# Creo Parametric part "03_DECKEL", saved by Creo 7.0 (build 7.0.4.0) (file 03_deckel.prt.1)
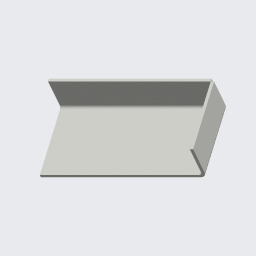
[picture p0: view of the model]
Units: millimeter Kilogram Sec (mmKs); MM, KILOGRAM, SECS
Materials in the file: S235JRG2

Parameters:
  SMT_PART_BEND_ALLOW_FACTOR_TYPE = "Y FACTOR"
  SMT_DFLT_RADIUS_SIDE = "Inside"
  SMT_DFLT_CRNR_REL_TYPE = "V Notch"
  SMT_DFLT_CRNR_REL_DEPTH_TYPE = "Blind"
  SMT_DFLT_BEND_REL_TYPE = "Rip"
  SMT_DFLT_BEND_REL_DEPTH_TYPE = "Up to Bend"
  SMT_DFLT_EDGE_TREA_TYPE = "Open"
  PTC_MATERIAL_NAME = "S235JRG2"
  MATERIAL = "S235JRG2"
  BENENNUNG = "XXX"
  DATUM = "XX.XX.XX"
  ERSTELLER = "ARINDA"
  TEILETYP = "Fertigungsteil"
  SELECT_EN_NAME = "S235JRG2"
  SELECT_DIN_NAME = "RSt37-2"
  SELECT_DIN_NUMBER = "1.0038"
  SELECT_ASTM_NAME = "A 283 M Grade 2"
  MATERIAL_GROUP = "ME_ST_Baustahl"
  STANDARD_EN_DELIVERYSPEC = "DIN EN 10025"
  STANDARD_DIN_DELIVERYSPEC = "DIN 17100"

Other parameters: SMT_THICKNESS, SMT_PART_BEND_ALLOWANCE_FACTOR, SMT_UPDATE_BEND_ALLOW_INFO, SMT_DFLT_BEND_RADIUS, SMT_DFLT_BEND_ANGLE, SMT_DFLT_CRNR_REL_WIDTH, SMT_DFLT_CRNR_REL_DEPTH, SMT_DFLT_BEND_REL_WIDTH, SMT_DFLT_BEND_REL_DEPTH, SMT_DFLT_BEND_REL_ANGLE, SMT_GAP, SMT_DFLT_EDGE_TREA_WIDTH, SMT_DFLT_MITER_CUT_WIDTH, SMT_DFLT_MITER_CUT_OFFSET, MASSE, SMT_DFLT_BEND_REL_LENGTH, D9, D11, D12, D13, D14, D15, D16, D17, D18, D19, D21, D24, D30, D34, D36, D37, D38, D39, D40, D41, D42, D43, D44, D49, D53, D55, D56, D57, D58, D59, D60, D61, D62, D63, D68, D72, D76, D77, D78, D79, D80, D81, D82, D83, D84, D85, D88, D96, D99, D103, D104, D105, D106

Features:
  1. coordinate system
  2. datum plane "DTM1", "T_RECHTS_Y-Z"
  3. datum plane "DTM2", "T_OBEN_X-Z"
  4. datum plane "DTM3", "T_VORNE_X-Y"
  5. datum axis "A_1"
  6. datum axis "A_2"
  7. datum axis "A_3"
  8. fill "Planar 1(Erste Lasche)"
  9. feature "Flange 1"
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
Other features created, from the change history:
  feature "Flange 2" (3 times)
  feature "Flach 1"

Other named items: T_BASIS, A_X-ACHSE, A_Y-ACHSE, A_Z-ACHSE

Layers: 00_STD-ACHSEN, 00_STD-EBENEN, 00_STD-KOORDSYS, KURVENELEMENTE, SAMMELFLÄCHEN, VOLUMENGEOMETRIE

Notes: V-Ausklinkung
